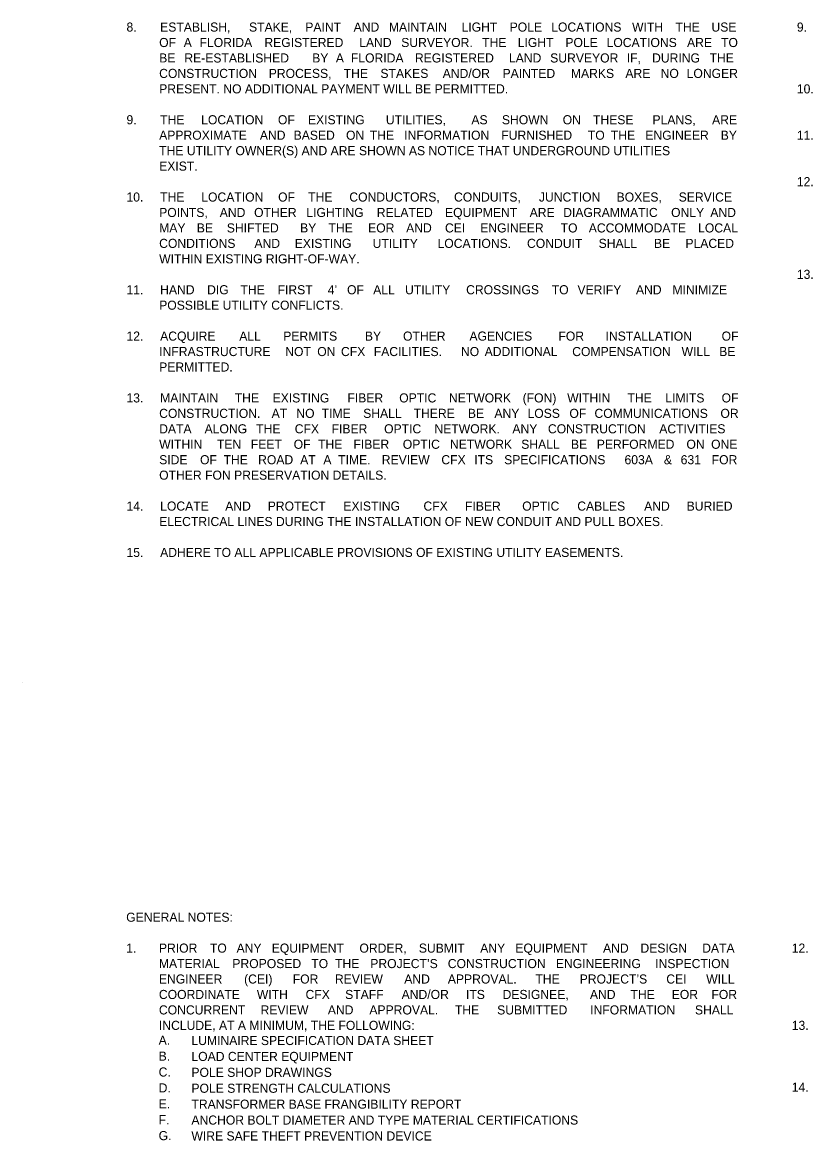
# Model space of a CAD drawing. Extents: x -55 to 2471539, y -90 to 3608906.
# Drawn here: x -54 to 555, y 780 to 1641 of the extents above; entities that cross this region are included whole.
import ezdxf

# ---------------------------------------------------------------- set-up
doc = ezdxf.new("R2010")
doc.units = 0
doc.layers.add('TextMinor', color=7, linetype='Continuous')
doc.layers.add('XSCell', color=7, linetype='Continuous')

msp = doc.modelspace()

# ---------------------------------------------------------------- linework, layer by layer
at = {"layer": 'TextMinor'}
msp.add_line((-54.3, 1133.16), (-54.3, 1133.16), dxfattribs=at)

# ---------------------------------------------------------------- texts
at = {"layer": 'XSCell'}
for s, p in [('8.', (25.93, 1634.2)), ('ESTABLISH, ', (51.88, 1634.2)), ('STAKE, ', (120.37, 1634.2)), ('PAINT ', (163.7, 1634.2)), ('AND ', (200.95, 1634.2)), ('MAINTAIN ', (228.11, 1634.2)), ('LIGHT ', (284.09, 1634.2)), ('POLE ', (321.15, 1634.2)), ('LOCATIONS ', (353.19, 1634.2)), ('WITH ', (415.49, 1634.2)), ('THE ', (448.94, 1634.2)), ('USE ', (476.64, 1634.2)), ('9.', (542.46, 1634.16)), ('OF ', (51.12, 1622.3)), ('A ', (70.02, 1622.3)), ('FLORIDA ', (82.24, 1622.3)), ('REGISTERED ', (132.19, 1622.3)), ('LAND ', (205.23, 1622.3)), ('SURVEYOR. ', (237.62, 1622.3)), ('THE ', (299.99, 1622.3)), ('LIGHT ', (327.38, 1622.3)), ('POLE ', (364.11, 1622.3)), ('LOCATIONS ', (395.84, 1622.3)), ('ARE ', (457.83, 1622.3)), ('TO ', (484.06, 1622.3)), ('BE ', (51.12, 1610.4)), ('RE-ESTABLISHED ', (70.53, 1610.4)), ('BY ', (169.03, 1610.4)), ('A ', (187.23, 1610.4)), ('FLORIDA ', (198.84, 1610.4)), ('REGISTERED ', (248.18, 1610.4)), ('LAND ', (320.61, 1610.4)), ('SURVEYOR ', (352.39, 1610.4)), ('IF, ', (411.39, 1610.4)), ('DURING ', (430.89, 1610.4)), ('THE ', (475.23, 1610.4)), ('CONSTRUCTION ', (51.12, 1598.5)), ('PROCESS, ', (135.53, 1598.5)), ('THE ', (193.29, 1598.5)), ('STAKES ', (221.6, 1598.5)), ('AND/OR ', (269.57, 1598.5)), ('PAINTED ', (315.68, 1598.5)), ('MARKS ', (368.35, 1598.5)), ('ARE ', (410.33, 1598.5)), ('NO ', (437.49, 1598.5)), ('LONGER ', (457.53, 1598.5)), ('PRESENT. NO ADDITIONAL PAYMENT WILL BE PERMITTED.', (51.12, 1586.6)), ('10.', (542.46, 1586.56)), ('9.', (25.93, 1562.8)), ('THE ', (51.88, 1562.8)), ('LOCATION ', (83.48, 1562.8)), ('OF ', (142.62, 1562.8)), ('EXISTING ', (165.74, 1562.8)), ('UTILITIES, ', (225.78, 1562.8)), ('AS ', (291.68, 1562.8)), ('SHOWN ', (315.2, 1562.8)), ('ON ', (362.04, 1562.8)), ('THESE ', (385.38, 1562.8)), ('PLANS, ', (431.2, 1562.8)), ('ARE ', (477.14, 1562.8)), ('APPROXIMATE ', (51.12, 1550.9)), ('AND ', (128.7, 1550.9)), ('BASED ', (154.72, 1550.9)), ('ON ', (195.09, 1550.9)), ('THE ', (213.38, 1550.9)), ('INFORMATION ', (239.94, 1550.9)), ('FURNISHED ', (314.71, 1550.9)), ('TO ', (381.43, 1550.9)), ('THE ', (399.16, 1550.9)), ('ENGINEER ', (425.72, 1550.9)), ('BY ', (483.8, 1550.9)), ('11.', (542.46, 1550.86)), ('THE UTILITY OWNER(S) AND ARE SHOWN AS NOTICE THAT UNDERGROUND UTILITIES ', (51.12, 1539)), ('EXIST.', (51.12, 1527.1)), ('12.', (542.46, 1515.16)), ('10.', (25.93, 1503.3)), ('THE ', (51.88, 1503.3)), ('LOCATION ', (83.55, 1503.3)), ('OF ', (142.75, 1503.3)), ('THE ', (165.94, 1503.3)), ('CONDUCTORS, ', (197.62, 1503.3)), ('CONDUITS, ', (278.3, 1503.3)), ('JUNCTION ', (343.7, 1503.3)), ('BOXES, ', (403.57, 1503.3)), ('SERVICE ', (451.42, 1503.3)), ('POINTS, ', (51.12, 1491.4)), ('OTHER ', (124.25, 1491.4)), ('LIGHTING ', (164.51, 1491.4)), ('EQUIPMENT ', (271.36, 1491.4)), ('DIAGRAMMATIC ', (362.44, 1491.4)), ('ONLY ', (445.54, 1491.4)), ('AND ', (97.78, 1491.4)), ('RELATED ', (218.76, 1491.4)), ('ARE ', (336.58, 1491.4)), ('AND ', (475.77, 1491.4)), ('MAY ', (51.12, 1479.5)), ('BE ', (80.1, 1479.5)), ('SHIFTED ', (103.22, 1479.5)), ('BY ', (159.71, 1479.5)), ('THE ', (181.63, 1479.5)), ('EOR ', (212.11, 1479.5)), ('AND ', (241.4, 1479.5)), ('CEI ', (271.34, 1479.5)), ('ENGINEER ', (298.47, 1479.5)), ('TO ', (360.47, 1479.5)), ('ACCOMMODATE ', (382.12, 1479.5)), ('LOCAL ', (466.36, 1479.5)), ('CONDITIONS ', (51.12, 1467.6)), ('AND ', (124.51, 1467.6)), ('EXISTING ', (155.55, 1467.6)), ('UTILITY ', (215.58, 1467.6)), ('LOCATIONS. ', (265.58, 1467.6)), ('CONDUIT ', (334.53, 1467.6)), ('SHALL ', (389.71, 1467.6)), ('BE ', (432.37, 1467.6)), ('PLACED ', (456.59, 1467.6)), ('WITHIN EXISTING RIGHT-OF-WAY.', (51.12, 1455.7)), ('13.', (542.46, 1443.76)), ('11.', (25.93, 1431.9)), ('HAND ', (51.88, 1431.9)), ('DIG ', (88.04, 1431.9)), ('THE ', (113.72, 1431.9)), ('FIRST ', (142.35, 1431.9)), ('4’ ', (180.98, 1431.9)), ('OF ', (195.88, 1431.9)), ('ALL ', (216.02, 1431.9)), ('UTILITY ', (240.58, 1431.9)), ('CROSSINGS ', (287.63, 1431.9)), ('TO ', (353.61, 1431.9)), ('VERIFY ', (373.41, 1431.9)), ('AND ', (418.48, 1431.9)), ('MINIMIZE ', (446.58, 1431.9)), ('POSSIBLE UTILITY CONFLICTS.', (51.12, 1420)), ('12.', (25.93, 1396.2)), ('ACQUIRE ', (51.88, 1396.2)), ('ALL ', (112.83, 1396.2)), ('PERMITS ', (146.69, 1396.2)), ('BY ', (209.63, 1396.2)), ('OTHER ', (239, 1396.2)), ('AGENCIES ', (290.18, 1396.2)), ('FOR ', (358.74, 1396.2)), ('INSTALLATION ', (395.06, 1396.2)), ('OF ', (484.48, 1396.2)), ('INFRASTRUCTURE ', (51.12, 1384.3)), ('NOT ', (148.26, 1384.3)), ('ON ', (172.92, 1384.3)), ('CFX ', (191.2, 1384.3)), ('FACILITIES. ', (216.47, 1384.3)), ('NO ', (283.62, 1384.3)), ('ADDITIONAL ', (301.9, 1384.3)), ('COMPENSATION ', (369.37, 1384.3)), ('WILL ', (453.64, 1384.3)), ('BE ', (482.6, 1384.3)), ('PERMITTED.', (51.12, 1372.4)), ('13.', (25.93, 1348.6)), ('MAINTAIN ', (51.88, 1348.6)), ('THE ', (109.34, 1348.6)), ('EXISTING ', (138.52, 1348.6)), ('FIBER ', (196.14, 1348.6)), ('OPTIC ', (236.08, 1348.6)), ('NETWORK ', (274.38, 1348.6)), ('(FON) ', (331.18, 1348.6)), ('WITHIN ', (365.51, 1348.6)), ('THE ', (411.91, 1348.6)), ('LIMITS ', (441.09, 1348.6)), ('OF ', (484.48, 1348.6)), ('CONSTRUCTION. ', (51.12, 1336.7)), ('AT ', (137.78, 1336.7)), ('NO ', (156.79, 1336.7)), ('TIME ', (176.31, 1336.7)), ('SHALL ', (208.3, 1336.7)), ('THERE ', (247.17, 1336.7)), ('BE ', (288.98, 1336.7)), ('ANY ', (309.41, 1336.7)), ('LOSS ', (334.92, 1336.7)), ('OF ', (367.21, 1336.7)), ('COMMUNICATIONS ', (386.52, 1336.7)), ('OR ', (483.56, 1336.7)), ('DATA ', (51.12, 1324.8)), ('ALONG ', (86.11, 1324.8)), ('THE ', (125.89, 1324.8)), ('CFX ', (155.57, 1324.8)), ('FIBER ', (183.98, 1324.8)), ('OPTIC ', (224.42, 1324.8)), ('NETWORK. ', (263.22, 1324.8)), ('ANY ', (323.28, 1324.8)), ('CONSTRUCTION ', (350.66, 1324.8)), ('ACTIVITIES ', (436.44, 1324.8)), ('WITHIN ', (51.12, 1312.9)), ('TEN ', (95.6, 1312.9)), ('FEET ', (121.73, 1312.9)), ('OF ', (154.77, 1312.9)), ('THE ', (173.54, 1312.9)), ('FIBER ', (200.8, 1312.9)), ('OPTIC ', (238.82, 1312.9)), ('NETWORK ', (275.2, 1312.9)), ('SHALL ', (330.08, 1312.9)), ('BE ', (368.42, 1312.9)), ('PERFORMED ', (388.31, 1312.9)), ('ON ', (457.38, 1312.9)), ('ONE ', (476.37, 1312.9)), ('SIDE ', (51.12, 1301)), ('OF ', (82.6, 1301)), ('THE ', (100.74, 1301)), ('ROAD ', (127.36, 1301)), ('AT ', (159.76, 1301)), ('A ', (177.6, 1301)), ('TIME. ', (189.06, 1301)), ('REVIEW ', (222.63, 1301)), ('CFX ', (268.54, 1301)), ('ITS ', (293.89, 1301)), ('SPECIFICATIONS ', (316.92, 1301)), ('603A ', (409.66, 1301)), ('& ', (439.98, 1301)), ('631 ', (452.94, 1301)), ('FOR ', (476.84, 1301)), ('OTHER FON PRESERVATION DETAILS.', (51.12, 1289.1)), ('14.', (25.93, 1265.3)), ('LOCATE ', (51.88, 1265.3)), ('AND ', (102, 1265.3)), ('PROTECT ', (134.75, 1265.3)), ('EXISTING ', (193.03, 1265.3)), ('CFX ', (254.76, 1265.3)), ('FIBER ', (286.78, 1265.3)), ('OPTIC ', (330.84, 1265.3)), ('CABLES ', (373.25, 1265.3)), ('AND ', (424.79, 1265.3)), ('BURIED ', (457.54, 1265.3)), ('ELECTRICAL LINES DURING THE INSTALLATION OF NEW CONDUIT AND PULL BOXES.', (51.12, 1253.4)), ('15.', (25.93, 1229.6)), ('ADHERE TO ALL APPLICABLE PROVISIONS OF EXISTING UTILITY EASEMENTS.', (51.88, 1229.6)), ('GENERAL NOTES:', (25.72, 948.68)), ('1.', (25.72, 924.88)), ('PRIOR ', (50.92, 924.88)), ('TO ', (90.22, 924.88)), ('ANY ', (110.76, 924.88)), ('EQUIPMENT ', (137.83, 924.88)), ('ORDER, ', (205.4, 924.88)), ('SUBMIT ', (251.19, 924.88)), ('ANY ', (298.48, 924.88)), ('EQUIPMENT ', (325.55, 924.88)), ('AND ', (393.12, 924.88)), ('DESIGN ', (421.95, 924.88)), ('DATA ', (469.51, 924.88)), ('12.', (538.51, 924.88)), ('MATERIAL ', (50.92, 912.98)), ('PROPOSED ', (107.5, 912.98)), ('TO ', (168.31, 912.98)), ('THE ', (186.62, 912.98)), ('PROJECT’S ', (213.77, 912.98)), ('CONSTRUCTION ', (273.5, 912.98)), ('ENGINEERING ', (356.75, 912.98)), ('INSPECTION ', (433.29, 912.98)), ('ENGINEER ', (50.92, 901.08)), ('(CEI) ', (116.56, 901.08)), ('FOR ', (154.03, 901.08)), ('REVIEW ', (186.54, 901.08)), ('AND ', (239.95, 901.08)), ('APPROVAL. ', (273.53, 901.08)), ('THE ', (341.01, 901.08)), ('PROJECT’S ', (375.14, 901.08)), ('CEI ', (441.85, 901.08)), ('WILL ', (472.62, 901.08)), ('COORDINATE ', (50.92, 889.18)), ('WITH ', (126.38, 889.18)), ('CFX ', (163.91, 889.18)), ('STAFF ', (194.42, 889.18)), ('AND/OR ', (237.93, 889.18)), ('ITS ', (287.52, 889.18)), ('DESIGNEE, ', (315.71, 889.18)), ('AND ', (383.02, 889.18)), ('THE ', (414.26, 889.18)), ('EOR ', (446.05, 889.18)), ('FOR ', (476.64, 889.18)), ('CONCURRENT ', (50.92, 877.28)), ('REVIEW ', (129.22, 877.28)), ('AND ', (181.06, 877.28)), ('APPROVAL. ', (213.07, 877.28)), ('THE ', (278.98, 877.28)), ('SUBMITTED ', (311.52, 877.28)), ('INFORMATION ', (383.19, 877.28)), ('SHALL ', (463.94, 877.28)), ('INCLUDE, AT A MINIMUM, THE FOLLOWING:', (50.92, 865.38)), ('13.', (538.51, 865.38)), ('A.', (50.72, 853.98)), ('LUMINAIRE SPECIFICATION DATA SHEET', (75.97, 853.71)), ('B.', (50.72, 841.73)), ('LOAD CENTER EQUIPMENT', (75.97, 841.46)), ('C.', (50.72, 829.48)), ('POLE SHOP DRAWINGS', (75.97, 829.21)), ('D.', (50.72, 817.23)), ('POLE STRENGTH CALCULATIONS', (75.97, 816.96)), ('14.', (538.51, 817.78)), ('E.', (50.72, 804.98)), ('TRANSFORMER BASE FRANGIBILITY REPORT', (75.97, 804.71)), ('F.', (50.72, 792.73)), ('ANCHOR BOLT DIAMETER AND TYPE MATERIAL CERTIFICATIONS', (75.97, 792.46)), ('G.', (50.72, 780.48)), ('WIRE SAFE THEFT PREVENTION DEVICE', (75.97, 780.21))]:
    msp.add_text(s, height=7, dxfattribs=at).set_placement(p)

doc.saveas('drawing.dxf')
